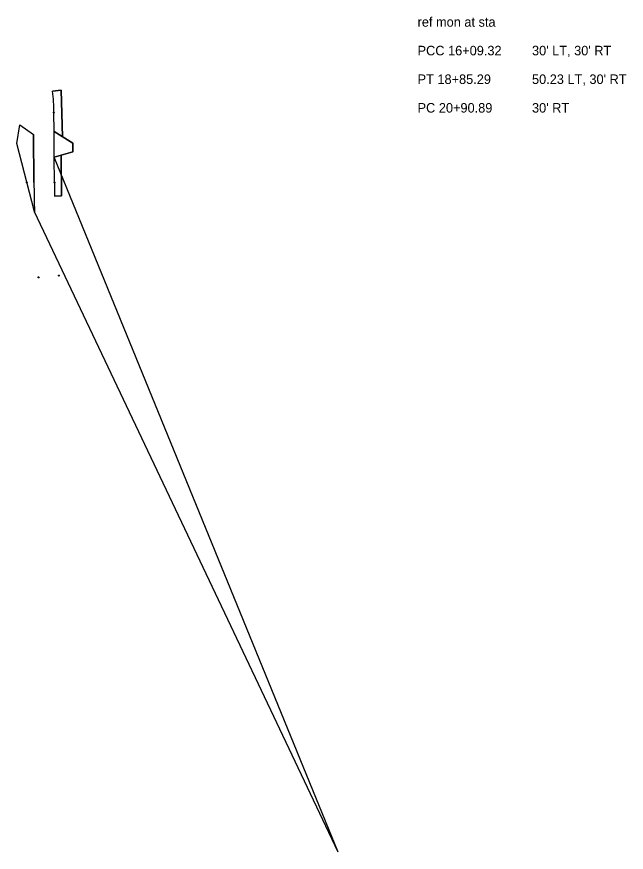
# Model space of a CAD drawing. Extents: x 2284354 to 2317587, y 513496 to 587560.
# Drawn here: x 2284354 to 2286144, y 585107 to 587560 of the extents above; entities that cross this region are included whole.
import ezdxf

# ---------------------------------------------------------------- set-up
doc = ezdxf.new("R2010")
doc.units = 0
for name, color, linetype in [('PV_X_EOP', 7, 'Continuous'), ('RS_Raster1', 7, 'Continuous'), ('RW_P_Esmt_SH', 7, 'Continuous'), ('RW_P_Esmt_TMP', 7, 'Continuous'), ('RW_P_Text', 7, 'Continuous'), ('SV_P_Control_Cells_Set', 7, 'Continuous')]:
    doc.layers.add(name, color=color, linetype=linetype)

msp = doc.modelspace()

# ---------------------------------------------------------------- linework, layer by layer
at = {"layer": 'PV_X_EOP'}
for centre in [(2284463.1, 587278.7), (2284383.6, 587072.6), (2284464.4, 587073.1), (2284417.8, 586794.6), (2284477.5, 586800)]:
    msp.add_circle(centre, 1.5, dxfattribs=at)
at = {"layer": 'RS_Raster1'}
for p, q in [((2284459, 587341.2), (2284483.8, 587344.3)), ((2284483.8, 587344.3), (2284488.6, 587207)), ((2284463.5, 587222.8), (2284463.1, 587278.7)), ((2284353.7, 587187.1), (2284363.3, 587242.5)), ((2284363.3, 587242.5), (2284403.5, 587213.7)), ((2284403.5, 587213.7), (2284404.4, 587072.7)), ((2284464, 587147.8), (2284463.5, 587222.8)), ((2284463.5, 587222.8), (2284518.7, 587188.2)), ((2284488.6, 587207), (2284463.5, 587222.8)), ((2284406.1, 586986.7), (2284353.7, 587187.1)), ((2284518.7, 587188.2), (2284518.9, 587163.2)), ((2284518.9, 587163.2), (2284464, 587147.8)), ((2284464, 587147.8), (2284483.9, 587153.4)), ((2284464.4, 587073.1), (2284464, 587147.8)), ((2284483.9, 587153.4), (2284484.9, 587033.5)), ((2284484.9, 587033.5), (2284464.9, 587033.2))]:
    msp.add_line(p, q, dxfattribs=at)
for centre, radius, start, end in [((2283936.5, 587275.2), 526.6, 0.3751, 7.195), ((2287766.9, 587094.7), 3362.6, 180.3751, 181.8415), ((2287766.9, 587094.7), 3302.6, 180.3751, 181.0679)]:
    msp.add_arc(centre, radius, start, end, dxfattribs=at)
at = {"layer": 'RW_P_Esmt_SH'}
for p, q in [((2284353.7, 587187.1), (2284363.3, 587242.5)), ((2284518.7, 587188.2), (2284463.5, 587222.8)), ((2284406.1, 586986.7), (2284353.7, 587187.1)), ((2284518.9, 587163.2), (2284518.7, 587188.2)), ((2284464, 587147.8), (2284518.9, 587163.2))]:
    msp.add_line(p, q, dxfattribs=at)
at = {"layer": 'RW_P_Esmt_TMP'}
for p, q in [((2284483.8, 587344.3), (2284459, 587341.2)), ((2284488.6, 587207), (2284483.8, 587344.3)), ((2284463.5, 587222.8), (2284463.1, 587278.7)), ((2284404.4, 587072.7), (2284403.5, 587213.7)), ((2284464.4, 587073.1), (2284464, 587147.8)), ((2284484.9, 587033.5), (2284483.9, 587153.4)), ((2284464.9, 587033.2), (2284484.9, 587033.5))]:
    msp.add_line(p, q, dxfattribs=at)
for centre, radius, start, end in [((2283936.5, 587275.2), 526.6, 0.3751, 7.195), ((2287766.9, 587094.7), 3362.6, 180.3751, 181.8415), ((2287766.9, 587094.7), 3302.6, 180.3751, 181.0679)]:
    msp.add_arc(centre, radius, start, end, dxfattribs=at)
at = {"layer": 'SV_P_Control_Cells_Set'}
for q in [(2284464, 587147.8), (2284406.1, 586986.7)]:
    msp.add_line((2285297.3, 585107.3), q, dxfattribs=at)

# ---------------------------------------------------------------- texts
at = {"layer": 'RW_P_Text'}
for s, p in [('ref mon at sta ', (2285530.9, 587530.1)), ('PCC 16+09.32', (2285530.9, 587446.1)), ("30' LT, 30' RT", (2285866.9, 587446.1)), ('PT 18+85.29', (2285530.9, 587362.1)), ("50.23 LT, 30' RT", (2285866.9, 587362.1)), ('PC 20+90.89', (2285530.9, 587278.1)), ("30' RT", (2285866.9, 587278.1))]:
    msp.add_text(s, height=28, dxfattribs=at).set_placement(p)

doc.saveas('drawing.dxf')
